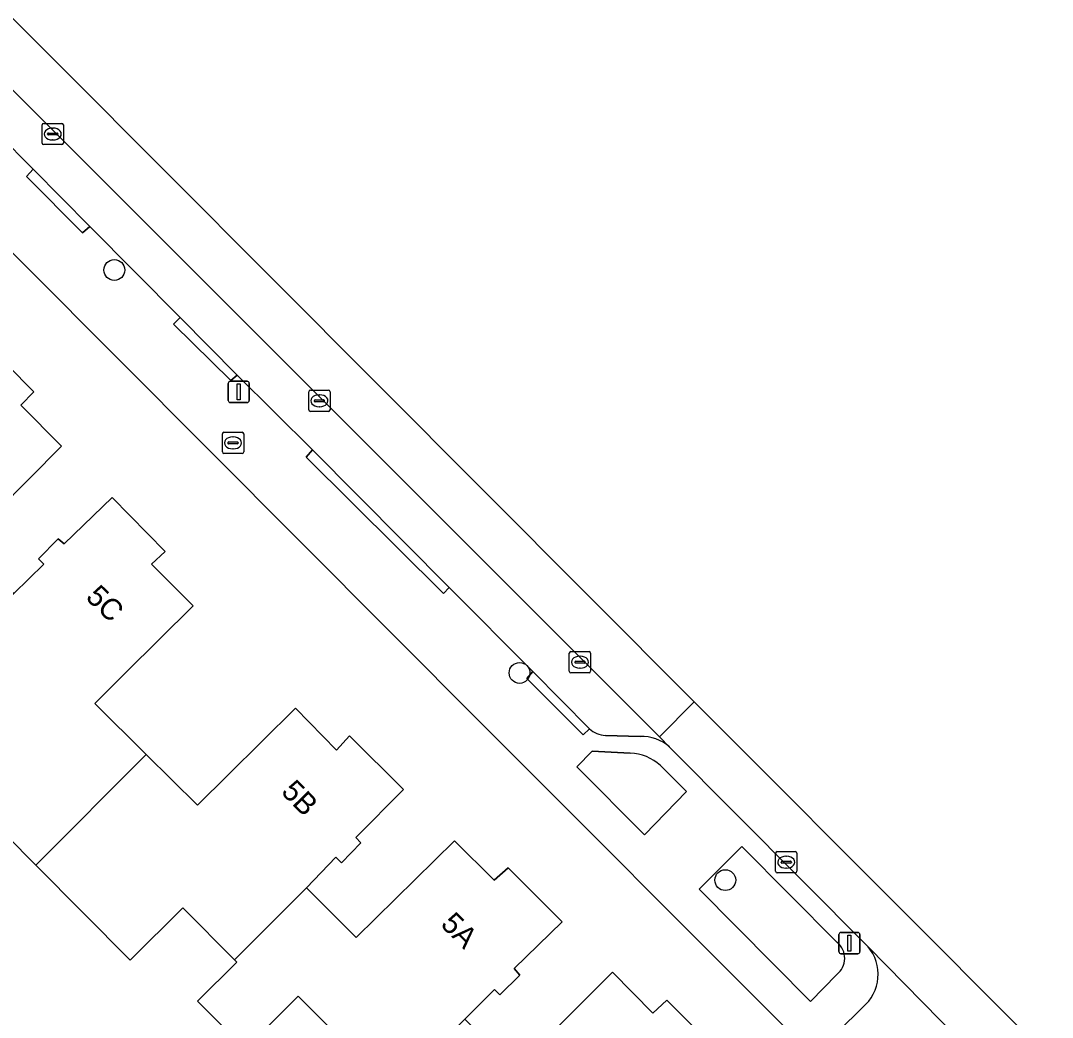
# Model space of a CAD drawing. Extents: x 159499 to 160349, y 382524 to 383273.
# Drawn here: x 160046.07 to 160094.54, y 383087.31 to 383134.14 of the extents above; entities that cross this region are included whole.
import ezdxf

# ---------------------------------------------------------------- set-up
doc = ezdxf.new("R2010")
doc.units = 0
for name, color, linetype in [('IMGEO_Boom', 7, 'Continuous'), ('IMGEO_Brandkraan', 7, 'Continuous'), ('IMGEO_Erf', 7, 'Continuous'), ('IMGEO_Fietspad_open', 7, 'Continuous'), ('IMGEO_Groenvoorziening', 7, 'Continuous'), ('IMGEO_Kolk', 7, 'Continuous'), ('IMGEO_Lichtmast', 7, 'Continuous'), ('IMGEO_Pand', 7, 'Continuous'), ('IMGEO_Pand_nummerreeks', 7, 'Continuous'), ('IMGEO_Parkeervlak_open', 7, 'Continuous'), ('IMGEO_Rijbaan_lokaal_open', 7, 'Continuous'), ('IMGEO_Voetpad_open', 7, 'Continuous')]:
    doc.layers.add(name, color=color, linetype=linetype)

msp = doc.modelspace()

# ---------------------------------------------------------------- linework, layer by layer
at = {"layer": 'IMGEO_Boom'}
for centre in [(160050.475, 383122.424), (160069.513, 383103.493), (160079.176, 383093.76)]:
    msp.add_circle(centre, 0.489, dxfattribs=at)
at = {"layer": 'IMGEO_Brandkraan'}
for p, q in [((160055.551, 383113.875), (160055.551, 383114.727)), ((160055.626, 383114.801), (160056.478, 383114.801)), ((160056.552, 383114.727), (160056.552, 383113.875)), ((160055.81, 383114.295), (160055.81, 383114.307)), ((160056.248, 383114.258), (160055.85, 383114.258)), ((160055.853, 383114.344), (160056.251, 383114.344)), ((160056.039, 383114.581), (160056.064, 383114.581)), ((160056.294, 383114.307), (160056.294, 383114.295)), ((160056.478, 383113.801), (160055.626, 383113.801)), ((160056.062, 383114.021), (160056.037, 383114.021))]:
    msp.add_line(p, q, dxfattribs=at)
for points in [[(160055.551, 383113.875), (160055.551, 383114.727)], [(160055.626, 383114.801), (160056.478, 383114.801)], [(160056.552, 383114.727), (160056.552, 383113.875)], [(160056.478, 383113.801), (160055.626, 383113.801)]]:
    msp.add_lwpolyline(points, dxfattribs=at)
for centre, radius, start, end in [((160055.628, 383114.725), 0.0765, 91.552, 178.448), ((160055.628, 383114.725), 0.0765, 91.552, 178.448), ((160056.476, 383114.725), 0.0765, 1.552, 88.448), ((160056.476, 383114.725), 0.0765, 1.552, 88.448), ((160055.85, 383114.304), 0.0403, 85.8775, 175.7526), ((160055.847, 383114.294), 0.0366, 178.938, 274.7102), ((160056.251, 383114.301), 0.043, 264.8664, 352.4533), ((160056.255, 383114.306), 0.0386, 1.7309, 96.639), ((160055.628, 383113.877), 0.0765, 181.552, 268.448), ((160055.628, 383113.877), 0.0765, 181.552, 268.448), ((160056.476, 383113.877), 0.0765, 271.552, 358.448), ((160056.476, 383113.877), 0.0765, 271.552, 358.448)]:
    msp.add_arc(centre, radius, start, end, dxfattribs=at)
for centre, major_axis, ratio, start_param, end_param in [((160056.038, 383114.301), (-0.387, 0.002), 0.722429, 4.712389, 7.853982), ((160056.063, 383114.301), (-0.39, 0.002), 0.717154, 1.570796, 4.712389)]:
    msp.add_ellipse(centre, major_axis=major_axis, ratio=ratio, start_param=start_param, end_param=end_param, dxfattribs=at)
at = {"layer": 'IMGEO_Erf'}
for points in [[(160069.07, 383073.156), (160071.919, 383076.914), (160077.006, 383081.993), (160081.991, 383086.829), (160067.75, 383101.08), (160016.301, 383152.744), (160001.274, 383140.9), (160002.826, 383138.938), (160000, 383136.696), (159969.339, 383112.369), (160000, 383073.962), (160006.879, 383065.344), (160051.214, 383033.728), (160053.92, 383031.798), (160060.452, 383040.944)], [(160044.168, 383119.245), (160046.692, 383116.707), (160046.077, 383116.072), (160047.989, 383114.149), (160043.439, 383109.554)], [(160045.76, 383107.219), (160047.17, 383108.6), (160046.917, 383108.851), (160047.844, 383109.794), (160048.12, 383109.556), (160050.377, 383111.741), (160052.869, 383109.201), (160052.229, 383108.605), (160054.178, 383106.641), (160051.002, 383103.494), (160049.558, 383102.063), (160051.976, 383099.664), (160054.378, 383097.28), (160055.82, 383098.706), (160058.986, 383101.836), (160060.914, 383099.872), (160061.53, 383100.544), (160064.06, 383098.014), (160061.817, 383095.759), (160062.063, 383095.503), (160061.144, 383094.576), (160060.877, 383094.832), (160059.496, 383093.403), (160061.839, 383091.063), (160066.449, 383095.597), (160068.314, 383093.763), (160068.974, 383094.338), (160071.521, 383091.806), (160069.252, 383089.609), (160069.519, 383089.3), (160068.585, 383088.376), (160068.328, 383088.622), (160066.949, 383087.227)], [(160056.383, 383086.067), (160054.39, 383088.076), (160056.236, 383089.906), (160056.126, 383090.017), (160053.701, 383092.462), (160051.215, 383089.997), (160046.784, 383094.465), (160042.61, 383098.674)], [(160070.721, 383086.274), (160073.877, 383089.428), (160075.773, 383087.508), (160076.427, 383088.124), (160078.97, 383085.587)], [(160063.498, 383083.939), (160059.116, 383088.311), (160057.181, 383086.372)]]:
    msp.add_lwpolyline(points, dxfattribs=at)
at = {"layer": 'IMGEO_Fietspad_open'}
for points in [[(160090.149, 383086.288), (160085.882, 383090.631)], [(160085.634, 383087.791), (160083.322, 383085.497), (160074.881, 383077.118)]]:
    msp.add_lwpolyline(points, dxfattribs=at)
msp.add_arc((160084.348, 383089.334), 2.009, 309.8131, 40.2056, dxfattribs=at)
at = {"layer": 'IMGEO_Groenvoorziening'}
for points in [[(160074.71, 383099.73), (160072.924, 383099.811), (160072.21, 383099.078), (160075.381, 383095.892), (160077.357, 383097.919), (160076.129, 383099.139)], [(160084.44, 383090.823), (160079.956, 383095.334), (160077.943, 383093.336), (160083.186, 383088.057), (160084.417, 383089.33)]]:
    msp.add_lwpolyline(points, dxfattribs=at)
for centre, radius, start, end in [((160074.603, 383097.473), 2.26, 47.503, 87.2745), ((160083.836, 383090.086), 0.953, 307.5638, 50.671)]:
    msp.add_arc(centre, radius, start, end, dxfattribs=at)
at = {"layer": 'IMGEO_Kolk'}
for p, q in [((160047.083, 383128.388), (160047.083, 383129.24)), ((160047.158, 383129.314), (160048.01, 383129.314)), ((160048.084, 383129.24), (160048.084, 383128.388)), ((160047.342, 383128.808), (160047.342, 383128.82)), ((160047.78, 383128.771), (160047.382, 383128.771)), ((160047.385, 383128.857), (160047.783, 383128.857)), ((160047.571, 383129.094), (160047.596, 383129.094)), ((160047.826, 383128.82), (160047.826, 383128.808)), ((160048.01, 383128.314), (160047.158, 383128.314)), ((160047.594, 383128.534), (160047.569, 383128.534)), ((160059.609, 383115.853), (160059.609, 383116.705)), ((160059.684, 383116.779), (160060.536, 383116.779)), ((160060.61, 383116.705), (160060.61, 383115.853)), ((160059.868, 383116.273), (160059.868, 383116.285)), ((160060.306, 383116.236), (160059.908, 383116.236)), ((160059.911, 383116.322), (160060.309, 383116.322)), ((160060.097, 383116.559), (160060.122, 383116.559)), ((160060.352, 383116.285), (160060.352, 383116.273)), ((160060.536, 383115.779), (160059.684, 383115.779)), ((160060.12, 383115.999), (160060.095, 383115.999)), ((160071.924, 383104.498), (160072.776, 383104.498)), ((160071.849, 383103.572), (160071.849, 383104.424)), ((160072.108, 383103.992), (160072.108, 383104.004)), ((160072.151, 383104.041), (160072.549, 383104.041)), ((160072.337, 383104.278), (160072.362, 383104.278)), ((160072.592, 383104.004), (160072.592, 383103.992)), ((160072.85, 383104.424), (160072.85, 383103.572)), ((160072.776, 383103.498), (160071.924, 383103.498)), ((160072.546, 383103.955), (160072.148, 383103.955)), ((160072.36, 383103.718), (160072.335, 383103.718)), ((160081.54, 383094.174), (160081.54, 383095.026)), ((160081.615, 383095.1), (160082.467, 383095.1)), ((160082.028, 383094.88), (160082.053, 383094.88)), ((160082.541, 383095.026), (160082.541, 383094.174)), ((160081.799, 383094.594), (160081.799, 383094.606)), ((160082.237, 383094.557), (160081.839, 383094.557)), ((160081.842, 383094.643), (160082.24, 383094.643)), ((160082.051, 383094.32), (160082.026, 383094.32)), ((160082.283, 383094.606), (160082.283, 383094.594)), ((160082.467, 383094.1), (160081.615, 383094.1))]:
    msp.add_line(p, q, dxfattribs=at)
for points in [[(160047.083, 383128.388), (160047.083, 383129.24)], [(160047.158, 383129.314), (160048.01, 383129.314)], [(160048.084, 383129.24), (160048.084, 383128.388)], [(160048.01, 383128.314), (160047.158, 383128.314)], [(160059.609, 383115.853), (160059.609, 383116.705)], [(160059.684, 383116.779), (160060.536, 383116.779)], [(160060.61, 383116.705), (160060.61, 383115.853)], [(160060.536, 383115.779), (160059.684, 383115.779)], [(160071.924, 383104.498), (160072.776, 383104.498)], [(160071.849, 383103.572), (160071.849, 383104.424)], [(160072.85, 383104.424), (160072.85, 383103.572)], [(160072.776, 383103.498), (160071.924, 383103.498)], [(160081.54, 383094.174), (160081.54, 383095.026)], [(160081.615, 383095.1), (160082.467, 383095.1)], [(160082.541, 383095.026), (160082.541, 383094.174)], [(160082.467, 383094.1), (160081.615, 383094.1)]]:
    msp.add_lwpolyline(points, dxfattribs=at)
for centre, radius, start, end in [((160047.16, 383129.238), 0.0765, 91.552, 178.448), ((160047.16, 383129.238), 0.0765, 91.552, 178.448), ((160048.008, 383129.238), 0.0765, 1.552, 88.448), ((160048.008, 383129.238), 0.0765, 1.552, 88.448), ((160047.382, 383128.817), 0.0403, 85.8775, 175.7526), ((160047.379, 383128.807), 0.0366, 178.938, 274.7102), ((160047.783, 383128.814), 0.043, 264.8664, 352.4533), ((160047.787, 383128.819), 0.0386, 1.7309, 96.639), ((160047.16, 383128.39), 0.0765, 181.552, 268.448), ((160047.16, 383128.39), 0.0765, 181.552, 268.448), ((160048.008, 383128.39), 0.0765, 271.552, 358.448), ((160048.008, 383128.39), 0.0765, 271.552, 358.448), ((160059.686, 383116.703), 0.0765, 91.552, 178.448), ((160059.686, 383116.703), 0.0765, 91.552, 178.448), ((160060.534, 383116.703), 0.0765, 1.552, 88.448), ((160060.534, 383116.703), 0.0765, 1.552, 88.448), ((160059.908, 383116.282), 0.0403, 85.8775, 175.7526), ((160059.905, 383116.272), 0.0366, 178.938, 274.7102), ((160060.309, 383116.279), 0.043, 264.8664, 352.4533), ((160060.313, 383116.284), 0.0386, 1.7309, 96.639), ((160059.686, 383115.855), 0.0765, 181.552, 268.448), ((160059.686, 383115.855), 0.0765, 181.552, 268.448), ((160060.534, 383115.855), 0.0765, 271.552, 358.448), ((160060.534, 383115.855), 0.0765, 271.552, 358.448), ((160071.926, 383104.422), 0.0765, 91.552, 178.448), ((160071.926, 383104.422), 0.0765, 91.552, 178.448), ((160072.774, 383104.422), 0.0765, 1.552, 88.448), ((160072.774, 383104.422), 0.0765, 1.552, 88.448), ((160072.148, 383104.001), 0.0403, 85.8775, 175.7526), ((160072.145, 383103.991), 0.0366, 178.938, 274.7102), ((160072.549, 383103.998), 0.043, 264.8664, 352.4533), ((160072.553, 383104.003), 0.0386, 1.7309, 96.639), ((160071.926, 383103.574), 0.0765, 181.552, 268.448), ((160071.926, 383103.574), 0.0765, 181.552, 268.448), ((160072.774, 383103.574), 0.0765, 271.552, 358.448), ((160072.774, 383103.574), 0.0765, 271.552, 358.448), ((160081.617, 383095.024), 0.0765, 91.552, 178.448), ((160081.617, 383095.024), 0.0765, 91.552, 178.448), ((160082.465, 383095.024), 0.0765, 1.552, 88.448), ((160082.465, 383095.024), 0.0765, 1.552, 88.448), ((160081.839, 383094.603), 0.0403, 85.8775, 175.7526), ((160081.836, 383094.593), 0.0366, 178.938, 274.7102), ((160082.24, 383094.6), 0.043, 264.8664, 352.4533), ((160082.244, 383094.605), 0.0386, 1.7309, 96.639), ((160081.617, 383094.176), 0.0765, 181.552, 268.448), ((160081.617, 383094.176), 0.0765, 181.552, 268.448), ((160082.465, 383094.176), 0.0765, 271.552, 358.448), ((160082.465, 383094.176), 0.0765, 271.552, 358.448)]:
    msp.add_arc(centre, radius, start, end, dxfattribs=at)
for centre, major_axis, ratio, start_param, end_param in [((160047.57, 383128.814), (-0.387, 0.002), 0.722429, 4.712389, 7.853982), ((160047.595, 383128.814), (-0.39, 0.002), 0.717154, 1.570796, 4.712389), ((160060.096, 383116.279), (-0.387, 0.002), 0.722429, 4.712389, 7.853982), ((160060.121, 383116.279), (-0.39, 0.002), 0.717154, 1.570796, 4.712389), ((160072.336, 383103.998), (-0.387, 0.002), 0.722429, 4.712389, 7.853982), ((160072.361, 383103.998), (-0.39, 0.002), 0.717154, 1.570796, 4.712389), ((160082.027, 383094.6), (-0.387, 0.002), 0.722429, 4.712389, 7.853982), ((160082.052, 383094.6), (-0.39, 0.002), 0.717154, 1.570796, 4.712389)]:
    msp.add_ellipse(centre, major_axis=major_axis, ratio=ratio, start_param=start_param, end_param=end_param, dxfattribs=at)
at = {"layer": 'IMGEO_Lichtmast'}
for p, q in [((160055.825, 383116.299), (160055.825, 383117.099)), ((160055.825, 383117.099), (160055.825, 383116.299)), ((160055.925, 383117.199), (160056.715, 383117.199)), ((160056.715, 383117.199), (160055.925, 383117.199)), ((160056.815, 383117.099), (160056.815, 383116.299)), ((160056.815, 383116.299), (160056.815, 383117.099)), ((160056.715, 383116.199), (160055.925, 383116.199)), ((160055.925, 383116.199), (160056.715, 383116.199)), ((160084.512, 383090.401), (160084.512, 383091.201)), ((160084.512, 383091.201), (160084.512, 383090.401)), ((160084.612, 383091.301), (160085.402, 383091.301)), ((160085.402, 383091.301), (160084.612, 383091.301)), ((160085.502, 383091.201), (160085.502, 383090.401)), ((160085.502, 383090.401), (160085.502, 383091.201)), ((160085.402, 383090.301), (160084.612, 383090.301)), ((160084.612, 383090.301), (160085.402, 383090.301))]:
    msp.add_line(p, q, dxfattribs=at)
for points in [[(160056.245, 383117.074), (160056.395, 383117.074), (160056.395, 383116.324), (160056.245, 383116.324), (160056.245, 383117.074)], [(160084.932, 383091.176), (160085.082, 383091.176), (160085.082, 383090.426), (160084.932, 383090.426), (160084.932, 383091.176)]]:
    msp.add_lwpolyline(points, dxfattribs=at)
for centre, start, end in [((160055.925, 383117.099), 90, 180), ((160055.925, 383117.099), 90, 180), ((160056.715, 383117.099), 0, 90), ((160056.715, 383117.099), 360, 90), ((160055.925, 383116.299), 180, 270), ((160055.925, 383116.299), 180, 270), ((160056.715, 383116.299), 270, 0), ((160056.715, 383116.299), 270, 0), ((160084.612, 383091.201), 90, 180), ((160084.612, 383091.201), 90, 180), ((160085.402, 383091.201), 0, 90), ((160085.402, 383091.201), 360, 90), ((160084.612, 383090.401), 180, 270), ((160084.612, 383090.401), 180, 270), ((160085.402, 383090.401), 270, 0), ((160085.402, 383090.401), 270, 0)]:
    msp.add_arc(centre, 0.1, start, end, dxfattribs=at)
at = {"layer": 'IMGEO_Pand'}
for points in [[(160047.989, 383114.149), (160046.077, 383116.072), (160046.692, 383116.707), (160044.168, 383119.245), (160041.984, 383116.966), (160041.669, 383117.242), (160040.749, 383116.34), (160040.99, 383116.079), (160039.586, 383114.674), (160036.228, 383111.34), (160036.311, 383111.257), (160038.846, 383108.701), (160036.851, 383106.723), (160036.843, 383102.926), (160039.147, 383100.602), (160042.399, 383103.856), (160045.76, 383107.219), (160043.439, 383109.554)], [(160054.178, 383106.641), (160052.229, 383108.605), (160052.869, 383109.201), (160050.377, 383111.741), (160048.12, 383109.556), (160047.844, 383109.794), (160046.917, 383108.851), (160047.17, 383108.6), (160045.76, 383107.219), (160042.399, 383103.856), (160042.56, 383103.694), (160045.095, 383101.138), (160042.61, 383098.674), (160046.784, 383094.465), (160051.976, 383099.664), (160049.558, 383102.063), (160051.002, 383103.494)], [(160046.784, 383094.465), (160051.215, 383089.997), (160053.701, 383092.462), (160056.126, 383090.017), (160059.496, 383093.403), (160060.877, 383094.832), (160061.144, 383094.576), (160062.063, 383095.503), (160061.817, 383095.759), (160064.06, 383098.014), (160061.53, 383100.544), (160060.914, 383099.872), (160058.986, 383101.836), (160055.82, 383098.706), (160054.378, 383097.28), (160051.976, 383099.664)], [(160069.519, 383089.3), (160069.252, 383089.609), (160071.521, 383091.806), (160068.974, 383094.338), (160068.314, 383093.763), (160066.449, 383095.597), (160061.839, 383091.063), (160059.496, 383093.403), (160056.126, 383090.017), (160056.236, 383089.906), (160054.39, 383088.076), (160056.383, 383086.067), (160057.181, 383086.372), (160059.116, 383088.311), (160063.498, 383083.939), (160063.592, 383083.846), (160066.949, 383087.227), (160068.328, 383088.622), (160068.585, 383088.376)], [(160076.98, 383083.082), (160076.725, 383083.336), (160078.97, 383085.587), (160076.427, 383088.124), (160075.773, 383087.508), (160073.877, 383089.428), (160070.721, 383086.274), (160069.292, 383084.847), (160066.949, 383087.227), (160063.592, 383083.846), (160060.35, 383080.581), (160062.713, 383078.224), (160066.509, 383078.207), (160068.507, 383080.21), (160071.062, 383077.66), (160075.808, 383082.417), (160076.062, 383082.162)]]:
    msp.add_lwpolyline(points, close=True, dxfattribs=at)
at = {"layer": 'IMGEO_Parkeervlak_open'}
for points in [[(160076.557, 383100.013), (160076.086, 383100.485), (160022.535, 383154.053)], [(160023.491, 383150.457), (160039.036, 383134.817), (160041.708, 383132.149), (160046.658, 383127.167), (160049.325, 383124.473), (160053.562, 383120.199), (160056.249, 383117.477), (160059.79, 383113.973), (160066.209, 383107.501), (160070.134, 383103.56), (160072.795, 383100.861)], [(160073.543, 383100.556), (160075.18, 383100.504)]]:
    msp.add_lwpolyline(points, dxfattribs=at)
for centre, radius, start, end in [((160073.644, 383101.874), 1.322, 230.0213, 265.6119), ((160075.273, 383098.59), 1.917, 47.9561, 92.7942)]:
    msp.add_arc(centre, radius, start, end, dxfattribs=at)
at = {"layer": 'IMGEO_Rijbaan_lokaal_open'}
for points in [[(160001.127, 383207.052), (160008.427, 383178.634), (160009.286, 383175.416), (160010.148, 383172.703), (160019.26, 383157.562), (160022.535, 383154.053), (160076.086, 383100.485), (160077.721, 383102.136)], [(160077.721, 383102.136), (160033.061, 383146.941)], [(160094.542, 383085.26), (160088.778, 383091.043), (160077.721, 383102.136), (160076.086, 383100.485), (160076.557, 383100.013), (160085.882, 383090.631), (160090.149, 383086.288), (160092.834, 383083.599), (160094.542, 383085.26)]]:
    msp.add_lwpolyline(points, dxfattribs=at)
at = {"layer": 'IMGEO_Voetpad_open'}
for points in [[(160009.599, 383158.345), (160016.301, 383152.744), (160067.75, 383101.08), (160081.991, 383086.829), (160083.322, 383085.497), (160085.634, 383087.791)], [(160072.795, 383100.861), (160072.502, 383100.579), (160069.86, 383103.237), (160070.134, 383103.56), (160066.209, 383107.501), (160065.937, 383107.22), (160059.481, 383113.631), (160059.79, 383113.973), (160056.249, 383117.477), (160055.95, 383117.225), (160053.254, 383119.875), (160053.562, 383120.199), (160049.325, 383124.473), (160048.986, 383124.177), (160046.357, 383126.82), (160046.658, 383127.167), (160041.708, 383132.149)], [(160075.18, 383100.504), (160073.543, 383100.556)], [(160076.129, 383099.139), (160077.357, 383097.919), (160075.381, 383095.892), (160072.21, 383099.078), (160072.924, 383099.811), (160074.71, 383099.73)], [(160085.882, 383090.631), (160076.557, 383100.013)], [(160084.417, 383089.33), (160083.186, 383088.057), (160077.943, 383093.336), (160079.956, 383095.334)], [(160079.956, 383095.334), (160084.44, 383090.823)]]:
    msp.add_lwpolyline(points, dxfattribs=at)
for points in [[(160049.325, 383124.473), (160046.658, 383127.167), (160046.357, 383126.82), (160048.986, 383124.177)], [(160056.249, 383117.477), (160053.562, 383120.199), (160053.254, 383119.875), (160055.95, 383117.225)], [(160066.209, 383107.501), (160059.79, 383113.973), (160059.481, 383113.631), (160065.937, 383107.22)], [(160070.134, 383103.56), (160069.86, 383103.237), (160072.502, 383100.579), (160072.795, 383100.861)]]:
    msp.add_lwpolyline(points, close=True, dxfattribs=at)
for centre, radius, start, end in [((160073.644, 383101.874), 1.322, 230.0213, 265.6119), ((160075.273, 383098.59), 1.917, 47.9561, 92.7942), ((160074.603, 383097.473), 2.26, 47.503, 87.2745), ((160083.836, 383090.086), 0.953, 307.5638, 50.671), ((160084.348, 383089.334), 2.009, 309.8131, 40.2056)]:
    msp.add_arc(centre, radius, start, end, dxfattribs=at)

# ---------------------------------------------------------------- texts
at = {"layer": 'IMGEO_Pand_nummerreeks'}
for s, rotation, p in [('5C', 315.9854, (160049.086, 383106.999)), ('5B', 314.2298, (160058.27, 383097.869)), ('5A', 314.8395, (160065.76, 383091.637))]:
    msp.add_text(s, height=1, rotation=rotation, dxfattribs=at).set_placement(p)

doc.saveas('drawing.dxf')
